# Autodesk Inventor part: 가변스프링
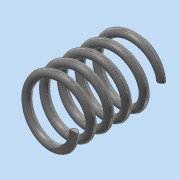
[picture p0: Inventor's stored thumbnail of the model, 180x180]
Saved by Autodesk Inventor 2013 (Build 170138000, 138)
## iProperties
Created: 2019-10
Part Number: 가변스프링
Material: 스테인리스강
Document SubType Name: Modeling
Designer: Administrator
Density: 8.08 g/cm^3
Mass: 147.816 g
Surface Area: 124.153 cm^2
Volume: 18.294 cm^3
Author: Administrator
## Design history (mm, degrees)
sketch "스케치1"
  geometry: L1 (0, 0)-(0, 67.25); L2 (0, 0)-(21, 0); L3 (0, 67.25)-(21, 67.25); C1 r 3 at (21, 0)
  constraints: 6 end point, 1 centre point, 1 coincident, 1 parallel, 1 perpendicular, 1 vertical
  dimensions: "d0" = 67.25 distance of L1.start L1.end (derived); "d1" = 21 distance of L1.start L2.end; "d2" = 21 distance of L1.end L3.end; "d3" = 6 diameter of C1
feature "코일1" sketch "스케치1" pitch "d4" = 10; turns "d6" = 5; dims "d5" = 67.25 (= d0), "d7" = 0, angle "d8" = 90 deg, angle "d9" = 90 deg, "d10" = 0, "d11" = 0
sketch "스케치2"
  geometry: L1 (67.25, 25)-(0, 25); L2 (0, 25)-(0, -25); L3 (0, -25)-(67.25, -25); L4 (67.25, -25)-(67.25, 25); 2 further points
  constraints: 8 end point, 2 parallel, 1 coincident, 1 horizontal, 1 midpoint, 1 perpendicular
  dimensions: "d12" = 67.25 distance of L1.start L1.end (= d0); "d14" = 50 distance of L3.end L1.start
extrude "돌출1" sketch "스케치2" stored distance "d15" = 0; taper "d16" = 0 deg
node "솔리드1"
